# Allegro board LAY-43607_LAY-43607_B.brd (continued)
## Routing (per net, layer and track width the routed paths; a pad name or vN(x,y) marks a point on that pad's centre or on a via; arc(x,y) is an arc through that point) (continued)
D1_MBG0: length 138.4
  TOP w0.137: v2(78.17,33.32) 77.74,33.32 77.49,33.07 76.53,33.07 76.37,33.23 76.37,33.37 76.21,33.54 75.98,33.54 75.82,33.37 75.82,33.23 75.66,33.07 74.4,33.07 73.23,34.23 72.87,34.23 72.66,34.45 72.66,34.96 U14.E27 ; R130.1 40.67,14.18 40.91,13.94 40.91,13.74 40.77,13.6 40.51,13.6 40.37,13.47 40.37,13.27 40.51,13.14 40.95,13.14 41.09,13 41.09,12.77 41.09,12.77 41.09,12.41 41.09,12.41 41.09,12.07 42.68,10.48 42.68,10.47 43.44,9.71 44.45,9.71 44.59,9.57 44.59,9.38 v1(44.52,9.31)
  L3_INT_1 w0.107: v1(90.44,9.31) 90.06,8.92 89.48,8.92 88.26,10.15 88.08,10.15 87.84,10.39 87.84,11.18 86.34,12.69 86.34,14.4 85.9,14.83 85.9,15.51 86.1,15.7 86.1,19.42 82.41,23.1 81.55,23.1 81.28,23.36 81.28,24.23 79.54,25.97 79.54,26.96 79.04,27.47 76.92,27.47 76.83,27.56 76.83,28.7 76.98,28.85 77.57,28.85 77.72,29.01 77.72,29.23 77.57,29.39 76.98,29.39 76.83,29.54 76.83,29.76 76.98,29.92 77.57,29.92 77.72,30.08 77.72,30.3 77.57,30.45 76.98,30.45 76.83,30.61 76.83,30.83 76.98,30.99 77.57,30.99 77.72,31.14 77.72,31.36 77.57,31.52 76.98,31.52 76.83,31.68 76.83,32.36 75.91,33.27 75.9,33.27 75.03,34.15 73.28,34.15 73.04,34.39 73.04,36.71 73.34,37.01 76.08,37.01 76.58,36.51 76.58,36.28 76.43,36.12 75.63,36.12 75.47,35.97 75.47,35.74 75.63,35.59 76.43,35.59 76.58,35.43 76.58,35.21 76.43,35.05 75.63,35.05 75.47,34.9 75.47,34.68 75.63,34.52 76.43,34.52 76.58,34.36 76.58,34.27 77.06,33.79 77.69,33.79 v2(78.17,33.32) ; v1(78.96,9.31) 78.96,9.57 78.58,9.95 78.58,10.37 78.45,10.51 77.7,10.51 77.59,10.61 77.59,10.99 77.78,11.17 77.78,11.18 78.17,11.57 78.17,11.9 77.96,12.11 77.16,12.11 76.97,12.29 76.73,12.29 76.55,12.11 76.3,12.11 76.12,12.29 75.88,12.29 75.69,12.11 75.45,12.11 75.27,12.29 75.02,12.29 74.84,12.11 74.6,12.11 74.41,12.29 74.17,12.29 73.99,12.11 71.67,12.11 71.58,12.2 70.93,12.2 70.83,12.11 70.15,12.11 69.86,11.82 69.86,10.34 68.41,8.89 68.11,8.89 67.69,9.31 v1(67.48,9.31) 67.48,9.58 67.3,9.77 67.12,9.77 67.06,9.82 67.06,10.31 66.85,10.52 66.52,10.52 66.51,10.53 65.35,10.53 63.3,8.49 63.3,7.2 63.11,7.01 62.1,7.01 61.79,7.31 61,7.31 60.89,7.42 60.89,7.58 60.78,7.68 60.57,7.68 60.46,7.58 60.46,7.42 60.36,7.31 59.85,7.31 59.68,7.48 59.68,7.88 59.27,8.29 59.27,8.44 59.66,8.83 59.66,8.98 59.51,9.13 59.36,9.13 58.97,8.74 58.82,8.74 58.65,8.91 56.65,8.91 56.25,9.31 v1(56,9.31)
  L4_INT_2 w0.107: v1(56,9.31) 55.77,9.31 55.37,8.9 55,8.9 54.57,9.34 53.04,9.34 52.71,9.02 52.71,7.22 52.61,7.11 52.21,7.11 51.61,7.72 49.85,7.72 49.48,8.09 48.36,8.09 47.84,7.57 47.16,7.57 46.48,8.26 46.48,8.75 46.3,8.92 44.52,8.92 44.41,9.04 44.41,9.19 v1(44.52,9.31)
  BOTTOM w0.137: v1(78.96,9.31) 79.2,9.31 79.6,8.91 79.61,8.91 79.61,8.91 79.93,8.91 80.19,8.65 80.85,8.65 81.88,7.62 82.47,7.62 82.77,7.31 83.13,7.31 83.51,7.69 88.14,7.69 88.21,7.75 88.22,7.75 88.23,7.76 88.35,7.76 88.96,8.37 88.96,8.48 89.39,8.91 89.81,8.91 90.04,8.67 90.04,8.34 90.28,8.11 90.61,8.11 90.84,8.34 90.84,8.91 v1(90.44,9.31)
D1_MBG1: length 99.9
  TOP w0.137: U14.E28 72.22,34.22 73.12,33.33 73.33,33.33 74.11,32.55 v2(82.18,32.55) ; R132.1 53.43,3.62 v2(56.32,3.62)
  L3_INT_1 w0.107: v2(82.18,32.55) 87.44,32.55 90.25,29.74 93.3,29.74 102.37,20.67 102.37,8.6 v2(98.89,5.12)
  L4_INT_2 w0.107: v2(98.89,5.12) 97.39,3.62 v2(56.32,3.62)
D1_MCAS_B: length 134.6
  TOP w0.137: v2(82.19,8.92) 82.3,8.92 82.32,8.91 83.36,8.91 U16.M8 83.91,9.31 84.31,9.71 85.01,9.71 85.3,10 86.84,10 86.97,10.14 86.97,10.7 87.11,10.83 87.38,10.83 87.52,10.7 87.52,10.14 87.66,10 88.21,10 88.5,9.71 91.99,9.71 92.18,9.9 92.38,9.9 93.46,8.82 93.65,8.82 93.84,9.01 93.84,9.2 92.76,10.28 92.76,10.48 93.21,10.92 93.86,10.92 94.28,10.51 94.6,10.51 94.84,10.27 94.84,9.79 94.93,9.7 95.1,9.7 95.24,9.56 v1(95.24,9.31) ; v2(95.51,21.77) 65.19,21.77 56.96,30 56.96,33.74 U14.AC28
  L3_INT_1 w0.107: v2(95.51,21.77) 96.58,21.77 98.36,19.99 98.36,11.84 96.25,9.72 95.66,9.72 v1(95.24,9.31)
  L4_INT_2 w0.107: v2(82.19,8.92) 79.59,8.92 79.35,9.16 79.35,9.49 79.12,9.72 78.03,9.72 77.78,9.47 77.78,9.3 77.38,8.89 77.14,8.89 77.04,9 77.04,9.26 76.93,9.36 76.72,9.36 76.61,9.26 76.61,9 76.5,8.89 76.29,8.89 76.18,9 76.18,9.26 76.04,9.39 75.89,9.39 75.75,9.26 75.75,9 75.65,8.89 75.43,8.89 75.33,9 75.33,9.26 75.19,9.39 75.04,9.39 74.9,9.26 74.9,9 74.79,8.89 74.58,8.89 74.47,9 74.47,9.26 74.34,9.39 74.19,9.39 74.05,9.26 74.05,9.03 73.94,8.92 72.75,8.92 72.36,9.31 v1(72.28,9.31) 71.87,9.72 64.52,9.72 64.18,9.38 64.18,7.57 64.07,7.46 63.59,7.46 63.46,7.59 63.46,7.92 63.05,8.33 63.05,9.36 62.69,9.72 61.21,9.72 v1(60.8,9.31)
  BOTTOM w0.137: v1(60.8,9.31) 60.37,8.88 57.71,8.88 57.68,8.91 56.64,8.91 56.4,8.66 56.4,8.34 56.17,8.11 55.85,8.11 55.84,8.11 55.84,8.11 55.6,7.87 55.6,7.87 55.6,7.86 55.6,7.54 55.37,7.31 55.04,7.31 54.81,7.54 54.31,7.54 53.99,7.22 53.99,6.51 53.84,6.36 53.47,6.36 53.33,6.5 53.33,6.84 51.98,8.19 50.67,8.19 50.52,8.34 50.52,8.67 50.29,8.91 49.72,8.91 v1(49.32,9.31) 48.92,8.91 47.81,8.91 46.78,7.88 46.78,4.79 R125.1
D1_MCKE0: length 136.9
  TOP w0.137: v2(79.56,34.59) 75.21,34.59 74.85,34.23 74.18,34.23 U14.C28 ; v1(44.52,10.91) 44.52,11.12 44.12,11.52 44.12,11.92 43.93,12.11 43.55,12.11 42.89,12.77 42.89,14.75 42.39,15.24 42.28,15.24 41.77,15.75 41.77,16.13 41.15,16.76 R131.1
  L3_INT_1 w0.107: v2(79.56,34.59) 80.64,34.59 80.81,34.76 80.81,36.22 80.62,36.41 79.17,36.41 79.02,36.25 79.02,36.01 78.86,35.85 78.64,35.85 78.48,36.01 78.48,36.25 78.33,36.41 77.98,36.41 77.88,36.3 77.88,35.09 79.84,33.13 79.84,32.14 80,31.98 82.18,31.98 82.31,31.85 82.31,31.58 82.18,31.45 80,31.45 79.84,31.29 79.84,31.07 80,30.92 82.18,30.92 82.33,30.76 82.33,30.54 82.18,30.38 80,30.38 79.84,30.23 79.84,29.61 80.69,28.76 80.91,28.76 81.89,29.75 82.11,29.75 82.27,29.59 82.27,29.37 81.28,28.39 81.28,28.17 81.44,28.01 81.66,28.01 82.65,29 82.87,29 83.02,28.84 83.02,28.62 82.04,27.63 82.04,27.41 82.19,27.26 82.42,27.26 83.4,28.24 83.62,28.24 83.78,28.09 83.78,27.86 82.8,26.89 82.8,26.74 88.68,20.85 88.68,20.49 88.56,20.37 88.17,20.37 88.04,20.24 88.04,20.06 88.17,19.94 88.56,19.94 88.68,19.81 88.68,14.42 88.99,14.11 89.38,14.11 89.62,13.87 89.62,12.71 90.04,12.29 90.04,11.66 90.44,11.26 v1(90.44,10.91) ; v1(44.52,10.91) 44.9,10.52 45.58,10.52 45.78,10.33 45.78,9.69 46.02,9.45 47.65,9.45 47.98,9.77 47.98,11.17 48.51,11.7 48.51,13.07 48.46,13.11 48.46,13.79 48.76,14.09 51.59,14.09 54.36,11.32 54.38,11.32 54.39,11.32 55.59,11.32 v1(56,10.91)
  L4_INT_2 w0.107: v1(56,10.91) 56.07,10.91 56.48,10.49 57.52,10.49 57.73,10.29 57.73,9.82 57.89,9.66 58.54,9.66 58.87,9.99 58.87,10.82 58.98,10.93 59.45,10.93 59.82,11.29 62.47,11.29 63.05,10.72 63.73,10.72 63.84,10.82 63.84,11.47 63.95,11.58 64.16,11.58 64.27,11.47 64.27,10.82 64.37,10.72 65.95,10.72 66.53,11.29 67.09,11.29 v1(67.48,10.91) 67.87,11.29 71.91,11.29 72.01,11.4 72.01,11.67 72.12,11.77 72.33,11.77 72.44,11.67 72.44,11.4 72.55,11.29 73.68,11.29 73.79,11.4 73.79,11.84 73.9,11.94 74.13,11.94 74.32,11.75 74.32,11.4 74.43,11.29 74.72,11.29 74.83,11.4 74.83,12.14 74.93,12.24 75.36,12.24 75.47,12.14 75.47,11.4 75.57,11.29 76.02,11.29 76.54,10.77 77.46,10.77 77.99,11.29 78.58,11.29 v1(78.96,10.91) 79.35,10.52 82.05,10.52 82.58,11.05 82.58,11.07 82.84,11.32 84.97,11.32 85.34,11.7 85.57,11.7 85.68,11.59 85.68,11.13 85.78,11.02 86,11.02 86.1,11.13 86.1,11.59 86.21,11.7 86.43,11.7 86.53,11.59 86.53,11.13 86.64,11.02 86.85,11.02 86.96,11.13 86.96,11.59 87.07,11.7 87.58,11.7 87.98,11.29 88.32,11.29 88.72,11.7 89.11,11.7 89.48,11.32 89.8,11.32 90.13,11.65 90.28,11.65 90.44,11.49 v1(90.44,10.91)
D1_MCLK0_N: length 131.7
  TOP w0.124: v2(89.32,25.92) 89.01,25.62 87.87,25.62 87.68,25.81 87.68,26.81 87.32,27.17 86.8,27.17 86.44,26.81 86.44,25.81 86.25,25.62 83.03,25.62 82.54,26.11 78.64,26.11 77.85,26.9 74.45,26.9 73.93,26.38 70.24,26.38 68.77,27.86 68.29,27.86 67.51,27.08 67.25,27.08 67.06,27.27 67.06,27.54 67.83,28.31 67.83,28.81 67.18,29.47 64.81,29.47 64.04,30.23 64.04,33.91 64.58,34.45 64.58,35.04 U14.R27
  L3_INT_1 w0.094: v1(95.24,10.91) 95.24,11.17 94.86,11.55 94.86,14.65 95.18,14.96 95.55,14.96 95.99,15.4 95.99,17.63 95.26,18.35 95.26,20.6 93.85,22.02 93.85,22.25 94.64,23.04 94.64,23.58 94.25,23.96 93.71,23.96 92.93,23.17 92.69,23.17 92.53,23.34 92.53,23.57 93.31,24.36 93.31,24.9 92.93,25.28 92.39,25.28 91.6,24.5 91.37,24.5 90.26,25.61 89.63,25.61 v2(89.32,25.92)
  BOTTOM w0.124: R137.1 45.97,5.01 45.97,5.75 46.41,6.19 46.41,8.14 47.64,9.37 47.64,9.87 48.27,10.51 48.92,10.51 v1(49.32,10.91) 49.57,10.91 49.96,10.52 50.46,10.52 50.69,10.75 51.01,10.75 51.64,11.38 53.26,11.38 53.52,11.64 53.52,12.16 53.9,12.54 54.15,12.54 54.6,12.1 56.74,12.1 57.19,11.65 57.19,10.23 57.76,9.67 59,9.67 59.84,10.5 60.44,10.5 60.8,10.86 v1(60.8,10.91) 61.19,10.52 61.76,10.52 62.23,10.98 64.04,10.98 64.83,11.78 66.72,11.78 68.53,13.58 69.64,13.58 69.89,13.34 69.89,12.05 71.09,10.85 71.09,10.75 71.32,10.52 71.89,10.52 v1(72.28,10.91) 72.03,11.15 72.03,11.97 72.16,12.09 72.79,12.09 72.82,12.12 74.52,12.12 74.65,11.99 74.65,11.58 74.92,11.31 75.48,11.31 75.79,11.62 75.79,11.99 75.91,12.12 79.14,12.12 79.5,12.47 80.61,12.47 82.57,10.52 83.26,10.52 83.5,10.75 83.61,10.75 v1(83.76,10.91) 83.76,11.09 83.48,11.37 83.48,11.81 83.84,12.17 85.74,12.17 85.86,12.04 85.86,11.5 86.17,11.19 86.81,11.19 87.13,11.5 87.13,12.04 87.25,12.17 89.77,12.17 90.64,11.3 91.4,11.3 91.42,11.28 91.92,11.28 92.69,10.51 94.49,10.51 94.5,10.52 94.6,10.52 94.61,10.52 94.86,10.52 v1(95.24,10.91)
D1_MCLK0_P: length 131.8
  TOP w0.124: U14.R28 63.74,34.11 63.74,34.08 63.72,34.06 63.72,30.1 64.68,29.15 67.05,29.15 67.51,28.68 67.51,28.44 66.74,27.67 66.74,27.14 67.12,26.76 67.65,26.76 68.42,27.54 68.63,27.54 70.11,26.06 74.06,26.06 74.58,26.58 77.71,26.58 78.51,25.79 82.41,25.79 82.9,25.3 86.38,25.3 86.76,25.67 86.76,26.68 86.93,26.85 87.18,26.85 87.36,26.68 87.36,25.67 87.74,25.3 89.03,25.3 v2(89.32,25.01)
  L3_INT_1 w0.094: v2(89.32,25.01) 89.54,25.24 90.1,25.24 91.22,24.13 91.76,24.13 92.54,24.91 92.78,24.91 92.94,24.75 92.94,24.52 92.16,23.73 92.16,23.19 92.54,22.8 93.08,22.8 93.87,23.59 94.1,23.59 94.26,23.43 94.26,23.19 93.48,22.4 93.48,21.86 94.89,20.45 94.89,18.2 95.62,17.47 95.62,15.55 95.4,15.33 95.02,15.33 94.49,14.8 94.49,11.89 94.49,11.4 94.86,11.03 94.86,10.58 94.76,10.48 94.52,10.48 94.44,10.56 v1(94.44,10.91)
  BOTTOM w0.124: R138.1 45.4,4.74 45.65,4.99 45.65,5.88 46.09,6.32 46.09,8.27 47.32,9.51 47.32,10.01 47.5,10.19 47.5,10.36 47.43,10.43 47.43,10.64 47.56,10.76 47.8,10.76 47.85,10.71 48.03,10.71 48.22,10.91 v1(48.52,10.91) 48.91,11.3 50.46,11.3 50.69,11.07 50.88,11.07 51.51,11.7 53.08,11.7 53.2,11.82 53.2,12.3 53.78,12.87 54.28,12.87 54.73,12.42 56.87,12.42 57.51,11.78 57.51,10.37 57.89,9.99 58.87,9.99 59.05,10.17 59.05,10.47 59.16,10.58 59.47,10.58 59.71,10.82 59.72,10.82 59.81,10.91 v1(60,10.91) 60.39,11.29 60.63,11.29 60.64,11.3 63.9,11.3 64.7,12.1 66.59,12.1 68.4,13.9 69.78,13.9 70.21,13.47 70.21,12.18 70.48,11.91 70.66,11.91 70.73,11.98 71.01,11.98 71.2,11.79 71.2,11.55 71.11,11.46 71.11,11.28 v1(71.48,10.91) 71.71,11.14 71.71,12.1 72.03,12.41 72.66,12.41 72.68,12.44 74.66,12.44 74.97,12.13 74.97,11.75 75.09,11.63 75.34,11.63 75.47,11.75 75.47,12.13 75.78,12.44 79.01,12.44 79.36,12.79 80.75,12.79 81.68,11.86 81.85,11.86 81.93,11.94 82.16,11.94 82.31,11.79 82.31,11.61 82.2,11.51 82.2,11.34 82.63,10.91 v1(82.96,10.91) 82.96,11.02 83.15,11.2 83.15,12.01 83.62,12.49 85.87,12.49 86.18,12.18 86.18,11.63 86.31,11.51 86.68,11.51 86.81,11.63 86.81,12.18 87.12,12.49 89.9,12.49 90.77,11.62 91.54,11.62 91.56,11.6 92.05,11.6 92.82,10.83 93.07,10.83 93.2,10.95 93.2,11.03 93.32,11.16 93.7,11.16 93.82,11.03 93.82,10.95 93.94,10.83 94.36,10.83 v1(94.44,10.91)
D1_MCS_B0: length 138.1
  TOP w0.137: U14.AB27 58.26,35.03 58.26,34.51 57.97,34.22 57.97,29.62 65.37,22.21 93.62,22.21 93.76,22.35 93.76,22.89 93.62,23.03 v2(91.35,23.03) ; v1(48.52,10.11) 48.4,10.11 48.12,10.39 47.29,10.39 46.26,9.36 46.26,5.17 45.62,4.54 45.62,4.34 45.88,4.08 R136.1 ; U16.L7 82.33,10.11 v2(82.33,10.1) 82.33,11.78 81.86,12.25 81.59,12.25 81.45,12.11 81.45,11.87 81.7,11.62 81.7,11.45 81.58,11.33 81.41,11.33 81.21,11.53 81.04,11.53 80.92,11.41 80.92,11.24 81.12,11.03 81.12,10.86 81,10.74 80.83,10.74 80.58,10.99 80.41,10.99 79.93,10.51 77.8,10.51 77.54,10.25 76.74,10.25 76.59,10.4 76.26,10.4 75.93,10.74 75.22,10.74 75.1,10.62 75.1,10.27 74.98,10.15 74.81,10.15 74.69,10.27 74.69,10.62 74.57,10.74 74.4,10.74 74.28,10.62 74.28,10.27 74.16,10.15 73.99,10.15 73.87,10.27 73.87,10.62 73.75,10.74 73.47,10.74 73.25,10.51 71.88,10.51 U565.L7 70.85,10.11 70.85,10.1 70.44,10.51 65.06,10.51 64.51,11.06 64.51,11.35 63.23,12.62 62.43,12.62 61.91,12.11 60.64,12.11 60.4,11.87 60.4,11.48 60.39,11.48 60.22,11.31 59.84,11.31 59.56,11.03 58.29,11.03 58.14,10.88 58.14,10.25 58.28,10.11 v1(60,10.11)
  L3_INT_1 w0.107: v2(91.35,23.03) 94.04,20.34 94.04,20.07 94.22,19.88 94.22,16.65 93.44,15.87 93.44,13.16 93.43,13.16 arc(93.44,13.11) 93.47,13.06 94.04,12.5 94.04,10.51 v1(94.44,10.11)
  BOTTOM w0.137: v1(48.52,10.11) 48.92,9.71 50.29,9.71 51.36,8.64 52.16,8.64 52.74,8.06 54.9,8.06 55.6,8.76 55.6,10.28 55.84,10.51 56.16,10.51 56.4,10.27 56.4,9.85 56.54,9.71 56.96,9.71 57.38,9.29 59.18,9.29 v1(60,10.11) ; v2(82.33,10.1) 83.19,10.1 83.6,10.51 85.86,10.51 85.87,10.52 86.84,10.52 86.87,10.55 87.39,10.55 88.02,11.18 88.87,11.18 89,11.31 89.9,11.31 90.04,11.17 90.04,10.75 90.28,10.51 91.36,10.51 91.37,10.51 91.41,10.51 91.8,10.11 92.17,10.11 92.31,9.96 92.31,9.48 92.45,9.34 92.71,9.34 92.85,9.48 92.85,9.97 92.99,10.11 v1(94.44,10.11)
D1_MDIC_0: length 2.9
  TOP w0.137: U14.P28 65.02,34.22 64.67,33.87 64.67,32.69 64.93,32.43 R141.2
D1_MDIC_1: length 2.9
  TOP w0.137: U14.U28 63.11,34.11 63.11,33.22 62.82,32.93 R140.2
D1_MDM0: length 45.7
  TOP w0.137: v2(84.42,33.76) 84.42,34.2 80.59,38.02 76.3,38.02 76.09,38.23 74.98,38.23 U14.B23 ; v2(93.88,14.89) 93.89,14.91 U15.E7
  L4_INT_2 w0.107: v2(84.42,33.76) 85.3,32.88 85.5,32.88 85.9,33.28 85.98,33.28 86.23,33.03 86.23,32.9 85.73,32.4 85.73,32.27 85.91,32.1 86.04,32.1 86.46,32.52 86.61,32.52 88.65,30.47 88.65,30.18 88.89,29.94 89.19,29.94 89.37,29.76 89.37,29.05 89.5,28.92 89.65,28.92 89.91,29.17 90.09,29.17 90.21,29.05 90.21,28.87 89.91,28.58 89.91,28.4 90.04,28.27 90.22,28.27 90.54,28.6 90.67,28.6 90.81,28.45 90.81,28.27 90.64,28.1 90.64,27.59 93.26,24.98 93.26,24.69 93.38,24.56 93.66,24.56 93.72,24.51 93.72,24.19 93.67,24.14 93.38,24.14 93.26,24.01 93.26,23.83 93.38,23.71 93.65,23.71 93.78,23.58 93.78,23.41 93.65,23.28 93.38,23.28 93.26,23.16 93.26,22.98 93.38,22.86 93.65,22.86 93.78,22.73 93.78,22.55 93.65,22.43 93.38,22.43 93.26,22.3 93.26,22.13 93.38,22 93.65,22 93.78,21.88 93.78,21.7 93.65,21.58 93.38,21.58 93.26,21.45 93.26,21.27 93.38,21.15 93.65,21.15 93.78,21.02 93.78,20.85 93.65,20.72 93.38,20.72 93.26,20.6 93.26,20.42 93.63,20.05 93.63,19.67 93.26,19.3 93.26,17.31 94.23,16.33 94.23,15.27 94.72,14.79 94.72,14.53 94.56,14.37 94.4,14.37 v2(93.88,14.89)
D1_MDM1: length 48.6
  TOP w0.137: U15.E2 90.84,14.51 91.55,14.51 92.02,14.98 92.57,14.98 92.61,15.01 v2(93,15.01) ; v3(69.42,39) U14.H22
  BOTTOM w0.137: v3(69.42,39) 69.7,39 70.07,38.62 70.35,38.62 70.6,38.37 70.6,38.05 70.86,37.79 71.27,37.79 71.41,37.66 71.41,37.22 71.63,37 71.99,37 72.22,36.76 72.22,36.49 72.25,36.46 72.25,36.44 72.47,36.22 72.79,36.22 73.02,35.99 73.02,35.63 72.63,35.24 72.63,33.32 78.9,27.05 78.9,27.03 81.35,24.57 84.22,24.57 87.62,21.18 87.62,14.84 87.99,14.46 88.44,14.46 88.8,14.11 89.5,14.11 89.64,13.97 89.64,13.44 89.78,13.31 90.28,13.31 90.44,13.14 90.44,12.64 90.58,12.51 91.18,12.51 91.82,11.86 92.56,11.86 93.19,12.5 93.22,12.5 93.44,12.72 93.44,12.91 93.33,13.03 93.33,13.81 93,14.14 v2(93,15.01)
D1_MDM2: length 49.1
  TOP w0.137: v3(72.63,36.59) U14.E25 ; U16.E7 v2(83.36,15.31)
  L4_INT_2 w0.107: v3(72.63,36.59) 73.01,36.21 73.01,35.7 73.28,35.44 74.11,35.44 74.83,36.15 76.74,36.15 76.87,36.03 76.87,30.22 82.02,25.07 82.02,23.98 82.46,23.54 82.61,23.54 83,23.94 83.15,23.94 83.3,23.79 83.3,23.63 82.91,23.24 82.91,23.09 83.06,22.94 83.21,22.94 83.61,23.33 83.76,23.33 83.91,23.18 83.91,23.03 83.52,22.64 83.52,22.49 86.25,19.75 86.69,19.75 86.84,19.6 86.84,19.31 86.74,19.2 85.96,19.2 85.86,19.09 85.86,18.88 85.96,18.77 86.74,18.77 86.84,18.66 86.84,18.45 86.74,18.34 85.96,18.34 85.86,18.24 85.86,18.02 85.96,17.92 86.74,17.92 86.84,17.81 86.84,17.6 86.74,17.49 85.96,17.49 85.86,17.38 85.86,17.17 85.96,17.06 86.74,17.06 86.84,16.96 86.84,15.71 86.71,15.58 86.03,15.58 85.87,15.42 85.87,14.91 86.03,14.75 86.69,14.75 86.75,14.69 86.75,13.63 86.47,13.35 85.63,13.35 85.41,13.58 85.41,14.82 85.3,14.92 84.68,14.92 84.57,14.82 84.57,14.2 84.46,14.09 83.89,14.09 83.74,14.23 83.74,14.67 83.74,14.67 83.74,14.92 v2(83.36,15.31)
D1_MDM3: length 46.5
  TOP w0.137: U14.J25 69.02,36.99 v3(69.43,36.59) ; v2(81.66,16.37) 82.56,15.47 82.56,13.94 82.39,13.77 82.13,13.77 81.96,13.94 81.96,15.12 81.78,15.31 79.36,15.31 U16.E2
  BOTTOM w0.137: v3(69.43,36.59) 69.43,36.49 69.84,36.09 69.84,35.45 69.71,35.32 69.71,33.37 70.19,32.89 70.19,31.8 70.41,31.58 70.61,31.58 70.92,31.9 71.14,31.9 71.34,31.7 71.34,31.44 71.04,31.14 71.04,30.95 73.47,28.53 73.47,28.25 73.26,28.05 73.26,26.73 73.6,26.39 74.19,26.39 74.38,26.58 74.38,27.76 74.52,27.9 74.79,27.9 74.93,27.76 74.93,26.53 75.06,26.39 75.4,26.39 75.54,26.53 75.54,26.87 75.67,27 75.95,27 76.08,26.87 76.08,26.53 76.22,26.39 76.56,26.39 76.7,26.26 76.7,24.78 77.04,24.45 77.83,24.45 80.39,21.88 82.49,21.88 83.4,20.97 83.4,20.68 83.6,20.49 83.78,20.49 83.91,20.35 83.91,20.08 83.78,19.94 83.54,19.94 83.4,19.8 83.4,17.63 82.31,16.53 82.31,16.24 81.67,15.6 81.4,15.6 81.26,15.74 81.26,16.24 81.4,16.38 81.66,16.38 v2(81.66,16.37)
D1_MDM4: length 47
  TOP w0.137: U14.V25 61.42,36.6 v3(61.42,36.59) ; U17.E7 v2(60.4,15.31)
  BOTTOM w0.137: v2(60.4,15.31) 60,15.31 59.83,15.48 59.83,17.01 60.13,17.31 60.83,17.31 60.92,17.22 60.92,16.9 61,16.82 61.39,16.82 61.53,16.96 61.53,17.75 61.45,17.82 60.95,17.82 60.8,17.98 60.8,18.79 61,18.99 62.3,18.99 62.98,19.68 62.98,20.38 63.47,20.87 64.06,20.87 64.3,20.64 64.75,20.64 65.04,20.93 65.04,21.58 64.86,21.76 63.85,21.76 63.53,22.09 63.53,22.6 63.38,22.75 62.76,22.75 62.6,22.59 62.6,20.37 62.46,20.24 62.23,20.24 62.05,20.42 62.05,22.59 61.89,22.75 61.51,22.75 61.3,22.96 61.3,23.62 61.43,23.75 62.79,23.75 62.93,23.89 62.93,24.13 62.76,24.3 61.43,24.3 61.3,24.44 61.3,24.71 61.43,24.85 62.76,24.85 62.9,24.99 62.9,25.21 62.71,25.4 61.43,25.4 61.3,25.54 61.3,25.81 61.43,25.95 62.36,25.95 62.52,26.1 62.52,26.63 62.33,26.81 61.78,26.81 61.66,26.94 61.66,27.36 61.52,27.5 61.32,27.5 61.19,27.64 61.19,27.91 61.32,28.05 61.52,28.05 61.66,28.19 61.66,29.37 61.52,29.51 61.52,30.75 61.3,30.97 61.3,31.3 61.55,31.56 61.55,31.81 61.3,32.07 61.3,32.39 61.55,32.65 61.55,32.84 61.16,33.24 61.16,33.62 61.43,33.9 61.43,34.07 61.31,34.19 61.22,34.19 61.1,34.31 61.1,34.48 61.22,34.6 61.31,34.6 61.43,34.72 61.43,34.99 61.03,35.39 61.03,36.46 61.16,36.59 v3(61.42,36.59)
D1_MDM5: length 46.8
  TOP w0.137: v3(57.42,38.19) 57.42,38.19 U14.AD24 ; U17.E2 v2(55.6,15.31)
  L4_INT_2 w0.107: v3(57.42,38.19) 57.07,37.84 55.68,37.84 55.65,37.86 51.09,37.86 50.71,37.48 50.71,34.09 50.3,33.68 50.3,33.25 50.62,32.93 52,32.93 52.29,33.22 52.95,33.22 53.69,32.48 53.69,25.63 52.44,24.38 52.44,17.22 51.83,16.61 51.83,12.75 51.46,12.39 51.46,11.23 51.6,11.09 52.05,11.09 52.18,11.23 52.18,12.26 52.46,12.54 53.31,12.54 54.09,13.32 54.09,15.46 54.32,15.69 55.22,15.69 v2(55.6,15.31)
D1_MDM6: length 47.6
  TOP w0.137: U18.E7 48.22,15.2 48.22,15.43 47.99,15.66 47.46,15.66 47.23,15.9 47.23,16.43 47.03,16.63 45.96,16.63 45.76,16.43 45.76,15.38 46.01,15.13 v2(47.63,15.13) ; U14.AC23 v3(57.42,38.99)
  BOTTOM w0.137: v3(57.42,38.99) 57.42,38.72 57.05,38.35 57.05,38.09 56.78,37.82 56.48,37.82 56.22,37.56 56.22,37.27 55.98,37.02 54.51,37.02 53.88,36.38 53.68,36.38 53.46,36.61 53.26,36.61 53.07,36.41 53.07,36.22 53.29,35.99 53.29,35.8 52.89,35.4 52.89,35.24 52.73,35.08 52.61,35.08 52.45,34.92 52.45,34.69 52.61,34.53 52.73,34.53 52.89,34.37 52.89,34.14 52.73,33.98 52.61,33.98 52.45,33.82 52.45,33.59 52.61,33.43 52.73,33.43 52.89,33.27 52.89,31.91 52.76,31.77 52.62,31.77 52.48,31.64 52.48,31.36 52.62,31.22 52.78,31.22 52.92,31.09 52.92,30.72 52.78,30.58 52.31,30.58 52.17,30.45 52.17,30.17 52.31,30.03 52.76,30.03 52.89,29.9 52.89,29.62 52.76,29.49 52.31,29.49 52.17,29.35 52.17,29.07 52.31,28.94 52.76,28.94 52.89,28.8 52.89,28.53 52.76,28.39 52.63,28.39 52.49,28.25 52.49,26.89 50.04,24.44 49.81,24.44 49.35,24.9 49.12,24.9 48.96,24.74 48.96,24.51 49.42,24.05 49.42,23.82 49.26,23.66 49.03,23.66 48.56,24.14 48.36,24.14 48.17,23.95 48.17,23.75 48.65,23.27 48.65,23.05 48.37,22.77 48.37,21.57 48.21,21.41 48,21.41 47.83,21.25 47.83,21.02 48,20.86 48.21,20.86 48.37,20.7 48.37,20.47 48.21,20.31 48,20.31 47.83,20.15 47.83,19.92 48,19.76 48.21,19.76 48.37,19.6 48.37,19.37 48.21,19.21 48,19.21 47.83,19.05 47.83,18.83 48,18.67 48.21,18.67 48.37,18.5 48.37,17.82 48.13,17.58 47.79,17.58 47.56,17.35 47.56,17.02 47.79,16.78 48.14,16.78 48.37,16.56 48.37,15.86 v2(47.63,15.13)
D1_MDM7: length 48.2
  TOP w0.137: U18.E2 v2(44.12,15.31) ; U14.AH24 53.42,37.39 52.58,37.39 50.02,34.84 v2(50.02,32.53)
  L4_INT_2 w0.107: v2(50.02,32.53) 50.02,31.39 50.84,30.57 50.84,30.14 50.99,29.99 51.21,29.99 51.37,29.83 51.37,29.61 51.21,29.45 50.99,29.45 50.84,29.3 50.84,29.08 50.99,28.92 51.24,28.92 51.39,28.76 51.39,28.54 51.24,28.39 50.99,28.39 50.84,28.23 50.84,27.04 49.5,25.71 49.5,25.28 49.65,25.13 50.1,25.13 50.25,24.97 50.25,24.75 50.1,24.59 49.65,24.59 49.5,24.44 49.5,24.22 49.65,24.06 50.1,24.06 50.25,23.9 50.25,23.68 50.1,23.53 49.65,23.53 49.5,23.37 49.5,23.15 49.65,22.99 50.1,22.99 50.25,22.84 50.25,22.62 50.1,22.46 49.65,22.46 49.5,22.3 49.5,22.08 49.65,21.93 50.1,21.93 50.25,21.77 50.25,21.55 50.1,21.39 49.65,21.39 49.5,21.24 49.5,21.02 49.65,20.86 50.1,20.86 50.25,20.7 50.25,20.48 50.1,20.33 49.65,20.33 49.5,20.17 49.5,19.18 49.06,18.74 49.06,16 48.56,15.51 45.83,15.51 44.92,14.6 44.92,13.8 44.81,13.69 43.54,13.69 43.3,13.45 43.3,12.13 43.1,11.94 42.13,11.94 41.92,12.15 41.92,14.87 42.75,15.7 43.73,15.7 v2(44.12,15.31)
D1_MDM8: length 49
  TOP w0.137: U565.E7 v2(71.88,15.31) ; U14.P24 65.42,37.4 v3(65.43,37.4)
  L4_INT_2 w0.107: v3(65.43,37.4) 65.43,37.12 65.84,36.7 65.84,34.59 65.73,34.48 65.35,34.48 65.24,34.38 65.24,34.18 65.36,34.06 65.73,34.06 65.84,33.95 65.84,33.12 65.59,32.87 65.59,32.69 65.77,32.51 65.77,32.3 66.32,31.76 66.32,31.59 65.93,31.2 65.93,31.05 66.07,30.91 66.22,30.91 66.62,31.3 66.77,31.3 66.88,31.2 66.88,31.05 66.57,30.74 66.57,30.41 66.67,30.3 67.02,30.3 67.32,30.6 67.47,30.6 67.77,30.3 68.63,29.44 68.63,29.44 68.79,29.28 68.79,27.9 68.69,27.79 68.06,27.79 67.95,27.68 67.95,27.47 68.06,27.36 68.69,27.36 68.84,27.2 68.84,26.32 69.09,26.08 69.09,23.68 69.27,23.5 70.21,23.5 70.37,23.34 70.37,23.14 70.26,23.03 69.84,23.03 69.73,22.92 69.73,22.71 69.84,22.6 70.26,22.6 70.37,22.5 70.37,22.28 70.26,22.18 69.84,22.18 69.73,22.07 69.73,21.86 69.84,21.75 70.26,21.75 70.37,21.64 70.37,21.43 70.26,21.32 69.84,21.32 69.73,21.22 69.73,21 69.84,20.9 70.26,20.9 70.37,20.79 70.37,20.58 70.26,20.47 69.84,20.47 69.73,20.36 69.73,19.88 69.92,19.69 71.21,19.69 71.32,19.58 71.32,19.37 71.21,19.26 69.84,19.26 69.73,19.16 69.73,18.99 69.93,18.79 71.11,18.79 71.31,18.58 71.31,17.06 71,16.75 70,16.75 69.7,16.45 68.94,16.45 68.84,16.35 68.84,16.02 68.97,15.89 70.01,15.89 70.12,15.78 70.12,15.57 70.01,15.46 69.38,15.46 69.27,15.35 69.27,14.96 69.48,14.75 70.2,14.75 70.46,15.01 70.46,16.11 70.79,16.44 71.04,16.44 71.25,16.22 71.25,14.74 71.36,14.63 71.46,14.63 71.88,15.05 v2(71.88,15.31)
D1_MDQ0: length 45.7
  TOP w0.137: v2(83.86,36.01) 83.86,36.06 80.96,38.95 76.26,38.95 76.23,38.98 74.24,38.98 U14.C22 ; U15.G2 v2(90.04,12.91)
  L4_INT_2 w0.107: v2(90.04,12.91) 90.46,12.49 91,12.49 91.78,11.72 93.52,11.72 93.74,11.94 93.74,12.71 93.23,13.23 93.23,14.69 93.39,14.85 93.39,15.17 93.23,15.33 93.23,15.66 93.52,15.95 93.52,16.59 92.93,17.18 92.93,18.97 92.79,19.12 92.79,24.87 88.72,28.94 88.72,29.09 88.28,29.53 88.28,29.99 86.9,31.36 86.07,31.36 83.37,34.05 83.37,35.53 v2(83.86,36.01)
D1_MDQ1: length 45.8
  TOP w0.137: v2(85.41,33.37) 85.41,33.84 80.74,38.51 76.26,38.51 76.17,38.6 U14.A23 ; U15.F7 94.42,14.09 v2(93.83,14.09)
  L4_INT_2 w0.107: v2(85.41,33.37) 84.69,34.08 84.69,34.31 85.04,34.65 85.19,34.65 86.16,33.68 86.17,33.68 89.09,30.75 89.23,30.75 89.47,30.51 89.47,30.37 91.48,28.36 91.48,28.19 91.31,28.02 91.31,27.84 91.43,27.72 91.61,27.72 91.78,27.89 91.96,27.89 92.08,27.76 92.08,27.58 91.99,27.49 91.99,27.32 92.13,27.18 92.28,27.18 92.39,27.28 92.56,27.28 92.69,27.16 92.69,26.98 92.44,26.73 92.44,26.58 92.57,26.46 92.77,26.46 92.99,26.68 93.17,26.68 93.29,26.55 93.29,26.38 93.06,26.14 93.06,25.99 93.17,25.88 93.4,25.88 93.59,26.07 93.77,26.07 94.13,25.72 94.13,24.36 94.19,24.29 94.19,20.68 94.04,20.53 94.04,19.26 94.41,18.89 94.41,16.63 94.78,16.26 94.78,15.28 94.96,15.1 94.96,13.12 94.75,12.92 94.52,12.92 94.35,13.1 94.35,13.96 94.24,14.06 94.24,14.06 94.21,14.09 v2(93.83,14.09)
D1_MDQ2: length 45.7
  TOP w0.137: U15.H3 v2(90.84,12.91) ; U14.C26 74.2,35.82 75.58,35.82 75.82,35.57 79.4,35.57 79.7,35.27 v2(79.75,35.27)
  L4_INT_2 w0.107: v2(79.75,35.27) 79.75,36.28 79.46,36.57 78.93,36.57 78.63,36.27 78.63,30.85 84.62,24.86 84.79,24.86 85.28,25.34 85.45,25.34 85.58,25.22 85.58,25.04 85.09,24.56 85.09,24.38 85.22,24.26 85.4,24.26 85.88,24.74 86.06,24.74 86.18,24.62 86.18,24.44 85.7,23.96 85.7,23.78 85.82,23.65 86,23.65 86.48,24.14 86.66,24.14 86.78,24.01 86.78,23.84 86.3,23.35 86.3,23.17 86.43,23.05 86.6,23.05 87.09,23.53 87.26,23.53 87.39,23.41 87.39,23.23 86.9,22.75 86.9,22.57 87.03,22.45 87.21,22.45 87.69,22.93 87.87,22.93 87.99,22.81 87.99,22.63 87.51,22.14 87.51,21.97 88.7,20.77 88.7,15.28 89.1,14.89 89.4,14.89 89.62,14.67 89.62,14.13 v2(90.84,12.91)
D1_MDQ3: length 45.7
  TOP w0.137: v2(79.04,35.13) 75.69,35.13 U14.A27 ; v2(92.32,12.26) 92.57,12.51 U15.H7
  L4_INT_2 w0.107: v2(79.04,35.13) 79.04,31.66 79.24,31.46 79.41,31.46 79.91,31.95 80.09,31.95 80.21,31.83 80.21,31.65 79.72,31.16 79.72,30.98 79.84,30.85 80.02,30.85 80.51,31.35 80.69,31.35 80.82,31.23 80.82,31.05 80.32,30.55 80.32,30.38 80.44,30.25 80.62,30.25 81.12,30.75 81.29,30.75 81.42,30.62 81.42,30.45 80.92,29.95 80.92,29.77 81.05,29.65 81.23,29.65 81.72,30.14 81.9,30.14 82.02,30.02 82.02,29.84 81.53,29.35 81.53,29.17 81.65,29.04 81.83,29.04 82.32,29.54 82.5,29.54 82.63,29.41 82.63,29.24 82.03,28.64 82.03,28.46 82.15,28.34 82.33,28.34 82.95,28.96 83.13,28.96 83.23,28.86 83.23,28.63 82.73,28.14 82.73,27.96 83.18,27.51 83.44,27.51 84.92,26.03 85.33,26.03 85.56,26.26 86.02,26.26 89.62,22.65 89.62,18.67 89.62,18.67 89.62,15.56 91.26,13.92 91.26,12.82 91.82,12.26 v2(92.32,12.26)
D1_MDQ4: length 45.8
  TOP w0.137: U14.B22 75,39.77 76.19,39.77 76.26,39.84 81.39,39.84 84.6,36.62 v2(84.6,35.82) ; U15.H2 v2(90.84,12.11)
  L4_INT_2 w0.107: v2(84.6,35.82) 84.89,35.53 85.03,35.53 89.88,30.68 89.88,30.57 94.52,25.93 94.52,25.9 94.54,25.89 94.54,24.53 94.6,24.47 94.6,21.05 95.21,20.44 95.21,18.24 95.64,17.8 95.64,15.05 95.26,14.67 95.26,13.1 93.6,11.43 91.52,11.43 v2(90.84,12.11)
D1_MDQ5: length 45.7
  TOP w0.137: v2(97.52,13.61) 97.5,13.59 97.5,12.44 97.17,12.11 95.64,12.11 U15.H8 ; v2(83.86,36.75) 81.21,39.39 76.26,39.39 76.25,39.4 U14.A22
  L4_INT_2 w0.107: v2(83.86,36.75) 84.4,36.75 90.29,30.86 90.29,30.74 96.05,24.99 96.05,24.55 95.92,24.43 95.39,24.43 95.29,24.32 95.29,24.11 95.39,24 95.92,24 96.05,23.88 96.05,23.7 95.92,23.57 95.22,23.57 95.09,23.44 95.09,23.27 95.21,23.15 95.92,23.15 96.05,23.02 96.05,14.29 96.35,13.99 97.14,13.99 v2(97.52,13.61)
D1_MDQ6: length 45.7
  TOP w0.137: U15.J3 91.93,12.4 v2(91.93,12.82) ; U14.B25 75.03,36.59 76.01,36.59 76.15,36.45 79.8,36.45 82.01,34.24 82.01,34.03 v2(81.96,33.98)
  L4_INT_2 w0.107: v2(81.96,33.98) 82.02,33.98 82.12,34.08 82.74,34.08 82.89,34.23 82.89,36.57 82.53,36.92 81.01,36.92 80.7,36.61 80.7,33.81 80.33,33.43 80.33,32.53 83.64,29.21 83.64,28.22 84.87,26.99 85.42,26.99 85.75,26.67 86.19,26.67 90.03,22.82 90.03,21.83 90.76,21.1 90.76,20.02 90.43,19.7 90.43,15.06 91.48,14.01 91.48,13.36 91.89,12.96 91.89,12.86 v2(91.93,12.82)
D1_MDQ7: length 45.8
  TOP w0.137: U14.A26 75.8,36.2 75.98,36.01 79.62,36.01 81.29,34.34 v2(81.29,32.97) ; v2(93.36,12.1) 94.05,12.1 U15.J7
  L4_INT_2 w0.107: v2(93.36,12.1) 92.91,12.1 92.7,12.3 92.7,12.69 91.7,13.69 91.7,14.99 91.2,15.49 91.2,15.5 90.85,15.86 90.85,19.49 91.2,19.84 91.2,21.24 90.44,22 90.44,22.99 86.36,27.08 85.98,27.08 85.65,27.41 85.04,27.41 84.05,28.39 84.05,29.39 80.74,32.7 80.74,33.26 81.11,33.64 81.11,36.16 81.39,36.44 82.2,36.44 82.48,36.17 82.48,35.94 82.35,35.81 82.3,35.81 82.19,35.7 82.19,35.49 82.3,35.38 82.35,35.38 82.48,35.26 82.48,34.68 82.36,34.56 81.67,34.56 81.54,34.43 81.54,33.64 81.29,33.38 v2(81.29,32.97)
D1_MDQ8: length 48.9
  TOP w0.137: v2(91.82,18.14) 92.11,18.42 92.11,18.94 91.91,19.14 91.38,19.14 91.24,19 U15.A3 ; v3(71.82,39) U14.E22
  BOTTOM w0.137: v3(71.82,39) 71.7,38.88 71.7,38.71 71.84,38.57 72.05,38.57 72.22,38.74 72.22,39.62 72.22,39.63 72.22,40.04 72.21,40.05 72.21,40.12 72.31,40.22 74.57,40.22 74.71,40.09 74.71,39.66 74.88,39.49 76.12,39.49 78.55,37.06 78.55,36.45 79.21,35.78 79.21,35.69 79.08,35.55 78.83,35.55 78.61,35.34 78.61,34.81 78.53,34.73 78.53,34.3 78.68,34.15 79.29,34.15 79.43,34.01 79.43,33.4 82.33,30.5 83.28,30.5 84.77,29.01 85.41,29.01 86.07,29.67 86.36,29.67 93.48,22.55 93.48,22.3 93.28,22.1 93.28,21.86 93.48,21.66 93.48,21.46 93.28,21.26 93.28,20.97 93.48,20.76 93.48,19.78 94.58,18.68 94.58,17.42 94.43,17.27 94.43,16.56 94.3,16.42 93.54,16.42 93.37,16.59 93.37,16.74 92.97,17.14 92.97,17.54 92.81,17.71 91.76,17.71 91.66,17.81 91.66,17.97 v2(91.82,18.14)
D1_MDQ9: length 48.7
  TOP w0.137: v2(93.8,18.8) 94.68,19.68 97.57,19.68 97.8,19.45 97.8,17.29 97.62,17.11 97.42,17.11 97.17,17.37 97.17,18.74 96.96,18.94 95.31,18.94 94.84,18.47 94.84,17.71 U15.B8 ; v3(72.62,39) U14.D22
  BOTTOM w0.137: v2(93.8,18.8) 93.77,18.8 92.83,19.74 92.83,21.8 92.74,21.89 92.74,22.59 92.6,22.72 92.35,22.72 92.22,22.59 92.06,22.59 91.88,22.78 91.88,22.97 92.04,23.14 92.04,23.36 91.51,23.9 91.28,23.9 91.12,23.74 90.87,23.74 90.73,23.88 90.73,24.13 90.89,24.29 90.89,24.51 90.73,24.67 90.5,24.67 90.34,24.51 90.12,24.51 89.81,24.82 89.81,25.36 89.68,25.5 89.14,25.5 88.89,25.75 88.89,26.51 86.84,28.57 84.59,28.57 83.1,30.06 82.15,30.06 78.09,34.12 78.09,36.88 75.73,39.24 74.78,39.24 74.77,39.25 73.7,39.25 73.55,39.4 73.03,39.4 v3(72.62,39)
D1_MDQ10: length 48.8
  TOP w0.137: U15.C3 90.84,16.91 90.84,19.09 91.17,19.42 92.21,19.42 92.39,19.25 92.39,18.71 92.52,18.58 92.8,18.58 92.92,18.71 92.92,19.32 93.15,19.55 93.15,19.95 93.02,20.08 90.99,20.08 90.43,19.52 v2(89.11,19.52) ; v3(71.82,38.2) U14.F23
  BOTTOM w0.137: v3(71.82,38.2) 72.22,37.8 72.22,37.23 72.45,37 72.86,37 73.03,36.83 73.03,36.48 73.05,36.45 73.05,36.32 73.2,36.17 73.58,36.17 73.8,35.95 73.8,35.64 73.58,35.42 73.16,35.42 72.99,35.24 72.99,33.69 81.62,25.05 85.64,25.05 85.83,24.87 85.83,24.64 85.42,24.23 85.42,24 85.58,23.84 85.81,23.84 86.22,24.25 86.44,24.25 86.61,24.09 86.61,23.86 86.19,23.45 86.19,23.22 86.35,23.06 86.58,23.06 86.99,23.47 87.22,23.47 87.38,23.31 87.38,23.09 86.97,22.67 86.97,22.45 87.13,22.29 87.36,22.29 87.77,22.7 88,22.7 88.16,22.54 88.16,22.31 87.75,21.9 87.75,21.67 87.91,21.51 88.13,21.51 88.55,21.92 88.77,21.92 89.11,21.58 89.11,21.25 88.95,21.09 88.31,21.09 88.15,20.92 88.15,20.7 88.31,20.54 88.95,20.54 89.11,20.38 v2(89.11,19.52)
D1_MDQ11: length 48.7
  TOP w0.137: U15.C7 93.91,16.51 93.32,17.1 93.32,19.11 v2(94.45,20.24) ; v3(71.02,38.2) U14.G23
  BOTTOM w0.137: v2(94.45,20.24) 94.45,22.83 86.73,30.55 86.4,30.55 84.11,32.85 83.92,32.85 83.76,32.69 83.76,31.81 83.59,31.63 83.2,31.63 83.06,31.77 83.06,32.84 82.92,32.97 82.2,32.97 81.54,33.64 81.54,34.14 81.4,34.27 80.89,34.27 80.73,34.43 80.73,34.66 80.89,34.82 81.49,34.82 81.63,34.96 81.63,35.3 81.48,35.44 80.8,35.44 80.64,35.6 80.64,35.95 80.37,36.22 80.02,36.22 79.86,36.38 79.86,36.61 79.96,36.7 79.96,36.93 76.02,40.86 73.43,40.86 73.05,41.24 73.05,41.51 72.77,41.79 71.69,41.79 71.45,41.55 71.45,41.29 71.16,41 70.9,40.99 70.65,40.75 70.65,38.84 70.87,38.62 71.08,38.62 71.16,38.55 71.16,38.33 v3(71.02,38.2)
D1_MDQ12: length 48.8
  TOP w0.137: U15.C2 90.84,16.11 91.41,16.11 91.64,16.34 91.64,16.35 91.78,16.49 v2(91.8,16.49) ; v3(70.22,39) U14.G22
  BOTTOM w0.137: v2(91.8,16.49) 92.35,16.49 92.67,16.17 94.68,16.17 95.24,16.73 95.24,19.31 94.93,19.63 94.93,22.97 86.91,30.99 86.59,30.99 75.78,41.8 73.26,41.8 73.02,42.03 73.02,42.32 72.75,42.6 71.66,42.6 71.4,42.33 71.4,42.01 71.16,41.77 70.87,41.77 70.6,41.5 70.6,41.23 70.33,40.97 70.07,40.97 69.82,40.72 69.82,39.4 v3(70.22,39)
D1_MDQ13: length 48.7
  TOP w0.137: v3(71.02,39) U14.F22 ; U15.C8 v2(94.84,16.91)
  BOTTOM w0.137: v2(94.84,16.91) 94.83,16.92 94.83,19.06 93.92,19.97 93.92,22.73 86.55,30.11 85.89,30.11 85.23,29.45 84.95,29.45 84.8,29.6 84.8,29.8 85.55,30.55 85.55,30.78 85.39,30.94 85.16,30.94 84.41,30.19 84.22,30.19 84.02,30.38 84.02,30.57 84.78,31.33 84.78,31.55 84.59,31.74 84.32,31.74 83.54,30.96 82.64,30.96 82.39,31.21 82.39,31.56 82.49,31.66 82.49,31.89 82.3,32.08 81.54,32.08 80.74,32.88 80.74,33.08 81.09,33.43 81.09,33.67 80.95,33.8 80.72,33.8 80.47,33.55 80.46,33.55 80.36,33.45 80.16,33.45 79.87,33.75 79.87,34.26 80.29,34.68 80.29,34.84 80.35,34.91 80.35,35.27 78.99,36.63 78.99,37.27 76.46,39.8 75.23,39.8 75.09,39.93 75.09,40.1 74.67,40.52 74.67,40.53 73.4,40.53 72.94,41 71.7,41 71.4,40.7 71.4,39.13 71.26,39 v3(71.02,39)
D1_MDQ14: length 48.7
  TOP w0.137: U15.D3 91.67,15.28 92.72,15.28 92.84,15.41 93.17,15.41 93.27,15.31 94.68,15.31 94.84,15.47 94.84,15.97 94.7,16.11 92.26,16.11 v2(91.89,15.74) ; v3(74.23,38.19) 73.83,37.8 U14.C24
  BOTTOM w0.137: v3(74.23,38.19) 73.85,37.82 73.85,37.24 74.1,36.99 74.39,36.99 74.86,36.52 75.09,36.52 75.62,37.05 75.85,37.05 76.01,36.89 76.01,36.67 75.48,36.13 75.48,35.9 75.91,35.48 75.91,32.04 81.95,25.99 86.17,25.99 91.27,20.88 91.27,18.38 90.89,17.99 90.89,17.76 91.23,17.42 91.23,17.2 91.07,17.04 90.84,17.04 90.5,17.38 90.27,17.38 90.08,17.18 90.08,16.77 90.44,16.41 90.44,15.8 90.58,15.66 90.63,15.66 90.68,15.71 91.01,15.71 91.32,15.39 91.32,15.21 90.94,14.83 90.94,14.63 91.24,14.34 91.46,14.34 91.76,14.63 91.76,14.9 92.17,15.31 92.17,15.45 v2(91.89,15.74)
D1_MDQ15: length 48.7
  TOP w0.137: U15.D7 v2(93.82,15.71) ; v3(72.62,38.2) U14.E23
  BOTTOM w0.137: v3(72.62,38.2) 73.01,37.81 73.01,37.23 73.24,37 73.59,37 73.82,36.76 73.82,36.28 74.05,36.05 74.05,35.86 74.43,35.48 75.37,35.48 75.59,35.26 75.59,33.45 75.47,33.33 75.47,33.32 75.25,33.1 75.25,32.06 81.79,25.51 86.02,25.51 90.82,20.71 90.82,18.61 90.32,18.11 89.88,18.11 89.64,17.87 89.64,16.63 89.52,16.51 89.01,16.51 88.78,16.28 88.78,15.64 88.66,15.51 88.15,15.51 88.06,15.42 88.06,15.02 88.17,14.91 90.25,14.91 90.44,14.72 90.44,13.55 90.6,13.39 91.91,13.39 92.04,13.52 92.04,14.62 92.28,14.85 92.29,14.85 92.84,15.41 93.23,15.41 93.46,15.18 93.46,14.75 93.71,14.5 94.14,14.5 94.32,14.67 94.32,15.61 94.22,15.71 v2(93.82,15.71)
D1_MDQ16: length 49.1
  TOP w0.137: v3(73.43,35.79) 73.02,36.2 U14.D26 ; U16.G2 v2(78.56,13.71)
  L4_INT_2 w0.107: v3(73.43,35.79) 73.43,36.1 73.53,36.21 74.38,36.21 74.74,36.57 74.97,36.57 75.12,36.71 75.4,36.71 75.55,36.57 75.83,36.57 75.97,36.71 76.25,36.71 76.4,36.57 76.95,36.57 77.28,36.24 77.28,32.52 77.38,32.41 77.51,32.41 77.61,32.3 77.61,32.09 77.51,31.98 77.38,31.98 77.28,31.88 77.28,31.66 77.38,31.56 77.51,31.56 77.61,31.45 77.61,31.24 77.51,31.13 77.38,31.13 77.28,31.02 77.28,30.4 84.53,23.14 84.53,22.49 84.7,22.33 84.7,22.17 84.63,22.11 84.63,21.95 84.78,21.8 84.93,21.8 85,21.87 85.15,21.87 85.3,21.72 85.3,21.57 85.23,21.5 85.23,21.35 85.39,21.2 85.54,21.2 85.61,21.27 85.76,21.27 85.91,21.12 85.91,20.97 85.84,20.9 85.84,20.75 85.99,20.6 86.14,20.6 86.21,20.67 86.36,20.67 87.25,19.77 87.25,14.29 87.23,14.27 87.23,13.04 87.12,12.93 85.48,12.93 85.12,13.29 83.2,13.29 82.93,13.02 82.61,13.02 82.5,13.13 82.5,14.72 82.39,14.83 82,14.83 81.89,14.72 81.89,13.13 81.79,13.02 81.42,13.02 81.32,13.13 81.32,13.43 81.19,13.55 79.98,13.55 79.87,13.66 79.87,14.05 79.74,14.18 79.57,14.18 79.44,14.05 79.44,13.54 79.34,13.43 79.11,13.43 78.84,13.71 v2(78.56,13.71)
D1_MDQ17: length 49.1
  TOP w0.137: U16.F7 v2(83.36,14.51)
  TOP w0.381: U14.E24 v3(72.63,37.39)
  L4_INT_2 w0.107: v2(83.36,14.51) 82.92,14.51 82.75,14.68 82.75,15.37 83.07,15.69 85.48,15.69 85.58,15.8 85.58,16.42 85.48,16.52 83.08,16.52 82.92,16.69 82.92,17.14 83.07,17.29 85.44,17.29 85.57,17.42 85.57,17.93 85.38,18.12 83.59,18.12 83.48,18.23 83.48,19.49 83.59,19.6 85.17,19.6 85.34,19.78 85.34,20.02 84.52,20.84 84.37,20.84 83.98,20.45 83.83,20.45 83.68,20.6 83.68,20.76 84.07,21.14 84.07,21.3 81.61,23.75 81.61,24.9 76.45,30.05 76.45,33.79 76.35,33.9 75.86,33.9 75.76,34.01 75.76,34.22 75.86,34.33 76.35,34.33 76.45,34.43 76.45,34.65 76.35,34.75 75.86,34.75 75.76,34.86 75.76,35.07 75.86,35.18 76.35,35.18 76.45,35.29 76.45,35.73 76.35,35.83 75.07,35.83 74.64,35.4 74.64,34.6 74.53,34.5 73.24,34.5 72.24,35.5 72.24,37.01 v3(72.63,37.39)
D1_MDQ18: length 49.2
  TOP w0.137: v3(71.03,37.39) 70.89,37.53 70.89,37.53 U14.G24 ; U16.H3 80.02,12.51 v2(80.45,12.08)
  L4_INT_2 w0.107: v3(71.03,37.39) 70.58,36.95 69.28,36.95 69.04,36.71 69.04,35.64 69.1,35.58 69.1,34.93 68.72,34.55 68.72,32.79 68.94,32.57 68.94,32.32 69.14,32.12 69.39,32.12 69.54,31.97 69.54,31.82 69.46,31.74 69.46,31.58 69.61,31.43 69.76,31.43 69.84,31.52 69.99,31.52 70.14,31.37 70.14,31.22 70.06,31.13 70.06,30.98 70.21,30.83 70.36,30.83 70.45,30.91 70.6,30.91 70.75,30.76 70.75,30.61 70.66,30.53 70.66,30.38 70.81,30.23 70.96,30.23 71.05,30.31 71.2,30.31 71.79,29.72 71.79,27.66 72,27.45 72.17,27.29 72.16,27.14 71.78,26.75 71.78,26.6 71.93,26.45 72.09,26.45 72.47,26.83 72.62,26.83 73.41,26.04 74.05,26.04 74.53,25.56 74.53,25.41 74.46,25.33 74.46,25.18 74.61,25.03 74.76,25.03 74.84,25.11 74.99,25.11 75.14,24.95 75.14,24.8 75.06,24.73 75.06,24.58 75.21,24.42 75.36,24.42 75.44,24.5 75.59,24.5 75.74,24.35 75.74,24.2 75.66,24.12 75.66,23.97 75.81,23.82 75.97,23.82 76.04,23.9 76.19,23.9 76.35,23.75 76.35,23.6 76.27,23.52 76.27,23.37 76.42,23.22 76.57,23.22 76.65,23.29 76.8,23.29 76.95,23.14 76.95,22.99 76.87,22.92 76.87,22.76 77.02,22.61 77.17,22.61 77.25,22.69 77.4,22.69 77.55,22.54 77.55,22.39 77.47,22.31 77.47,22.16 77.63,22.01 77.78,22.01 77.85,22.09 78,22.09 78.78,21.32 78.78,19.6 78.49,19.31 76.13,19.31 75.76,18.94 75.76,18.42 75.88,18.29 76.74,18.29 76.85,18.18 76.85,17.97 76.74,17.86 75.88,17.86 75.76,17.74 75.76,16.31 75.88,16.19 76.21,16.19 76.34,16.06 76.34,15.88 76.21,15.76 75.89,15.76 75.78,15.65 75.78,14.94 75.75,14.91 75.75,12.56 76.22,12.08 77.85,12.08 77.97,11.96 77.97,11.75 78.1,11.63 78.28,11.63 78.4,11.75 78.4,11.96 78.53,12.08 78.7,12.08 78.83,11.96 78.83,11.75 78.95,11.63 79.13,11.63 79.25,11.75 79.25,11.96 79.38,12.08 v2(80.45,12.08)
D1_MDQ19: length 49.1
  TOP w0.137: U14.H25 70.09,36.73 70.09,36.73 v3(70.23,36.59) ; U16.H7 v2(83.36,12.91)
  L4_INT_2 w0.107: v2(83.36,12.91) 82.03,11.57 81.21,11.57 81.01,11.78 81.01,12.27 80.79,12.49 77.54,12.49 77.53,12.49 77.15,12.49 76.9,12.75 76.9,14.06 77.31,14.47 77.31,14.71 77.16,14.85 76.27,14.85 76.19,14.92 76.19,15.2 76.27,15.27 77.2,15.27 77.34,15.42 77.34,16.57 77.19,16.72 76.29,16.72 76.18,16.82 76.18,17.04 76.29,17.14 77.16,17.14 77.28,17.26 77.28,18.63 77.29,18.64 77.29,18.66 77.63,19 78.06,19 78.18,18.88 78.18,18.35 78.42,18.11 78.71,18.11 79.03,18.43 79.03,19.14 79.33,19.45 80.25,19.45 80.33,19.52 80.33,20.28 80.22,20.39 79.91,20.39 79.45,19.93 79.29,19.93 79.19,20.04 79.19,20.27 79.64,20.73 79.64,21.03 74.22,26.46 73.58,26.46 73.31,26.73 73.31,27.37 72.98,27.7 72.83,27.7 72.66,27.53 72.5,27.53 72.35,27.68 72.35,27.83 72.52,28 72.52,28.15 72.2,28.47 72.2,29.89 69.34,32.75 69.34,33.66 69.24,33.77 69.08,33.77 68.98,33.87 68.98,34.09 69.08,34.2 69.24,34.2 69.34,34.3 69.34,35.14 69.84,35.63 69.84,36.46 69.97,36.59 v3(70.23,36.59)
D1_MDQ20: length 49.1
  TOP w0.137: U14.C25 73.83,37 v3(74.23,37.39) ; U16.H2 78.56,12.11 77.64,12.11 77.21,12.54 75.42,12.54 v2(74.78,13.19)
  L4_INT_2 w0.107: v2(74.78,13.19) 74.78,18.63 76.09,19.95 78.21,19.95 78.36,20.1 78.36,20.69 77.82,21.23 77.67,21.23 76.85,20.41 76.7,20.41 76.55,20.56 76.55,20.71 77.37,21.53 77.37,21.69 77.22,21.84 77.07,21.84 76.25,21.02 76.1,21.02 75.94,21.17 75.94,21.32 76.76,22.14 76.76,22.29 73.42,25.63 73.19,25.63 72.98,25.85 71.82,25.85 71.21,26.47 71.21,27.11 71.37,27.27 71.37,27.53 71.21,27.7 71.21,27.96 71.37,28.12 71.37,28.39 71.21,28.55 71.21,29.25 70.96,29.49 70.96,29.5 68.09,32.37 68.09,35.52 68.21,35.64 68.21,37.48 68.51,37.78 73.84,37.78 v3(74.23,37.39)
D1_MDQ21: length 49.1
  TOP w0.137: U16.H8 v2(84.16,12.91) ; v3(73.43,36.59) U14.D25
  L4_INT_2 w0.107: v2(84.16,12.91) 84.55,12.52 88.6,12.52 88.86,12.78 88.86,13.14 88.75,13.24 88.21,13.24 88.1,13.35 88.1,13.56 88.21,13.67 88.75,13.67 88.86,13.78 88.86,14.01 87.91,14.95 87.91,15.11 88.02,15.21 88.17,15.21 88.29,15.34 88.29,15.51 88.17,15.64 87.89,15.64 87.77,15.76 87.77,16.86 87.87,16.96 88.19,16.96 88.29,17.07 88.29,17.28 88.19,17.39 87.87,17.39 87.77,17.5 87.77,17.71 87.87,17.82 88.19,17.82 88.29,17.92 88.29,18.14 88.19,18.24 87.87,18.24 87.77,18.35 87.77,19.84 87.12,20.49 87.12,20.64 87.61,21.13 87.61,21.28 87.46,21.43 87.31,21.43 86.82,20.94 86.67,20.94 86.52,21.09 86.52,21.24 87.01,21.73 87.01,21.88 86.86,22.03 86.71,22.03 86.22,21.54 86.07,21.54 85.92,21.69 85.92,21.84 86.41,22.34 86.41,22.49 86.26,22.64 86.11,22.64 85.61,22.14 85.46,22.14 84.95,22.66 84.95,23.68 78.14,30.49 78.14,32.77 77.76,33.15 77.76,33.92 77.86,34.03 78.07,34.03 78.17,34.13 78.17,34.35 78.07,34.45 77.86,34.45 77.76,34.56 77.76,34.77 77.86,34.88 78.07,34.88 78.17,34.99 78.17,35.2 78.07,35.31 77.86,35.31 77.76,35.41 77.76,35.63 77.86,35.73 78.07,35.73 78.17,35.84 78.17,36.05 78.07,36.16 77.86,36.16 77.76,36.27 77.76,36.62 77.4,36.98 73.81,36.98 v3(73.43,36.59)
D1_MDQ22: length 49.1
  TOP w0.137: U14.G25 70.62,37 v3(71.03,36.59) ; v2(80.89,13.17) 81.29,13.57 81.98,13.57 82.02,13.52 82.27,13.52 82.41,13.38 82.41,13.08 82.26,12.93 81.97,12.93 81.54,12.5 81.43,12.5 80.62,11.68 79.79,11.68 U16.J3
  L4_INT_2 w0.107: v3(71.03,36.59) 70.64,36.21 70.64,35.49 70.77,35.36 70.77,34.06 71.09,33.75 71.45,33.75 71.65,33.95 72.19,33.95 72.3,33.85 72.3,32.71 72.47,32.54 72.62,32.54 73.26,33.18 73.41,33.18 73.68,32.92 73.68,32.77 73.04,32.12 73.04,31.97 73.49,31.51 73.49,28.35 74.27,27.57 74.42,27.57 74.63,27.77 74.78,27.77 74.93,27.62 74.93,27.47 74.72,27.27 74.72,27.12 74.87,26.96 75.03,26.96 75.23,27.17 75.38,27.17 75.53,27.02 75.53,26.87 75.33,26.66 75.33,26.51 75.48,26.36 75.63,26.36 75.83,26.57 75.99,26.57 76.14,26.42 76.14,26.27 75.93,26.06 75.93,25.91 81.44,20.4 81.44,20.29 81.55,20.18 81.89,20.18 81.99,20.07 81.99,19.86 81.89,19.75 81.55,19.75 81.44,19.65 81.44,19.17 80.93,18.66 80.48,18.66 79.8,17.99 79.8,17.21 80.69,16.32 80.69,16.17 80.44,15.91 80.28,15.91 79.68,16.51 79.53,16.51 79.38,16.36 79.38,16.17 80.14,15.41 80.14,15.26 80.04,15.15 79.76,15.15 79.04,15.87 78.89,15.87 78.78,15.76 78.78,15.6 79.17,15.22 79.17,14.86 78.98,14.67 78.98,14.53 78.98,14.53 78.98,14.35 78.72,14.09 78.39,14.09 78.16,13.86 78.16,13.46 78.45,13.17 v2(80.89,13.17)
D1_MDQ23: length 49.2
  TOP w0.137: U16.J7 v2(82.14,12.53) ; v3(70.23,35.79) 69.82,36.2 U14.H26
  L4_INT_2 w0.107: v3(70.23,35.79) 70.23,35.54 69.66,34.97 69.66,34.61 69.76,34.51 70.15,34.51 70.26,34.4 70.26,34.19 70.15,34.08 69.76,34.08 69.66,33.97 69.66,33.02 70.07,32.6 70.22,32.6 71.09,33.47 71.28,33.47 71.43,33.32 71.43,33.17 70.55,32.28 70.55,32.13 70.68,32 70.89,32 71.58,32.69 71.73,32.69 71.88,32.54 71.88,32.39 71.16,31.67 71.16,31.51 71.28,31.39 71.43,31.39 72.05,32.02 72.32,32.02 72.47,31.87 72.47,31.72 71.79,31.03 71.79,30.88 71.9,30.78 72.05,30.78 72.16,30.89 72.31,30.89 72.46,30.74 72.46,30.59 72.35,30.47 72.35,30.32 72.66,30.02 72.66,29.7 72.76,29.59 72.97,29.59 73.08,29.49 73.08,29.27 72.97,29.17 72.76,29.17 72.66,29.06 72.66,28.6 80.74,20.52 80.74,20.22 80.84,20.12 80.92,20.12 81.05,19.99 81.05,19.82 80.92,19.69 80.84,19.69 80.74,19.58 80.74,19.35 80.17,18.78 80.02,18.78 79.74,19.06 79.56,19.06 79.44,18.94 79.44,18.76 79.7,18.5 79.7,18.32 79.54,18.15 79.21,18.15 78.98,17.92 78.98,17.07 78.98,17.07 78.98,16.69 78.87,16.58 78.66,16.58 78.55,16.69 78.55,16.95 78.44,17.06 78.25,17.06 78.15,16.95 78.15,15.73 78.25,15.62 78.43,15.62 78.54,15.51 78.54,15.3 78.43,15.19 78.25,15.19 78.15,15.09 78.15,14.35 77.92,14.12 77.54,14.12 77.31,13.89 77.31,13.4 77.39,13.32 77.91,13.32 78.48,12.76 81.28,12.76 81.42,12.62 81.42,12 81.53,11.9 81.96,11.9 82.14,12.07 v2(82.14,12.53)
D1_MDQ24: length 46.4
  TOP w0.137: v3(68.63,38.19) 68.22,38.6 U14.K23 ; v2(84.8,19.21) 84.25,19.21 84.25,19.21 80.86,19.21 U16.A3
  BOTTOM w0.137: v3(68.63,38.19) 68.25,38.57 68.25,39.15 68.49,39.39 68.91,39.39 69.05,39.26 69.05,38.78 69.21,38.62 69.61,38.62 69.8,38.43 69.8,38.38 69.82,38.36 69.82,37.13 69.96,36.99 70.39,36.99 70.62,36.76 70.62,36.47 70.89,36.2 71.19,36.2 71.19,36.2 71.24,36.2 71.45,35.98 71.45,35.37 71.36,35.28 71.36,32.99 72.22,32.12 72.22,31.05 72.47,30.8 73.9,30.8 74.59,30.1 74.59,29.35 75.88,28.06 76.61,28.06 79.89,24.78 79.89,23.79 80.48,23.2 83.59,23.2 86.62,20.16 86.62,16.57 86.45,16.39 86.1,16.39 85.97,16.53 85.97,18.94 85.7,19.21 v2(84.8,19.21)
D1_MDQ25: length 46.5
  TOP w0.137: v3(69.43,37.39) 69.02,37.79 U14.J24 ; U16.B8 v2(84.16,17.71)
  BOTTOM w0.137: v3(69.43,37.39) 69.43,37.12 69.85,36.69 69.85,36.44 70.1,36.19 70.35,36.19 70.62,35.92 70.62,35.34 70.76,35.21 70.9,35.21 71.05,35.05 71.05,34.81 70.9,34.66 70.76,34.66 70.62,34.52 70.62,34.25 70.76,34.11 70.97,34.11 71.11,33.97 71.11,33.7 70.97,33.56 70.79,33.56 70.66,33.42 70.66,33 71.78,31.88 71.78,30.84 72.78,29.84 73.47,29.84 73.66,29.65 73.66,29.46 73.56,29.35 73.56,29.16 73.75,28.96 73.95,28.96 74.05,29.07 74.25,29.07 75.85,27.47 76.58,27.47 77.81,26.24 77.81,25.25 78.41,24.64 78.67,24.64 78.9,24.88 79.1,24.88 79.29,24.69 79.29,24.49 79.02,24.23 79.02,24.03 80.33,22.72 80.94,22.72 81.07,22.59 81.07,22.46 81.21,22.33 81.49,22.33 81.62,22.46 81.62,22.59 81.76,22.72 82.03,22.72 82.17,22.59 82.17,22.46 82.31,22.33 82.58,22.33 82.72,22.46 82.72,22.59 82.86,22.72 83.38,22.72 83.65,22.45 83.65,22.26 83.3,21.91 83.3,21.71 83.44,21.58 83.63,21.58 83.98,21.92 84.24,21.92 84.4,21.76 84.4,21.52 84.16,21.28 84.16,21.06 84.33,20.89 84.54,20.89 84.8,21.15 85.01,21.15 85.72,20.44 85.72,19.74 85.58,19.61 84.29,19.61 83.75,19.07 83.75,18.28 83.92,18.11 85.23,18.11 85.45,17.89 85.45,14.59 85.31,14.45 84.79,14.45 84.56,14.68 84.56,17.31 v2(84.16,17.71)
D1_MDQ26: length 46.4
  TOP w0.137: U16.C3 v2(79.36,16.91) ; v3(67.83,37.39) 67.42,37.79 U14.L24
  BOTTOM w0.137: v2(79.36,16.91) 79.1,16.91 78.96,17.05 78.96,18.85 78.5,19.31 76.66,19.31 76.26,18.92 76.26,15.82 76.4,15.69 77.12,15.69 77.23,15.58 77.23,15.3 77.1,15.17 76.15,15.17 76.01,15.03 76.01,14.58 75.49,14.05 74.39,14.05 74.26,14.19 74.26,14.42 74.38,14.55 74.85,14.55 74.97,14.67 74.97,14.86 74.81,15.03 74.4,15.03 74.32,15.11 74.32,19.7 73.96,20.06 72.16,20.06 72.16,20.06 70.21,20.06 69.49,20.78 69.49,27.14 66.78,29.86 66.78,31.64 66,32.42 66,35.35 65.8,35.55 65.8,36.74 66.06,37 67.19,37 67.59,37.4 67.82,37.4 v3(67.83,37.39)
D1_MDQ27: length 46.4
  TOP w0.137: U16.C7 v2(83.36,16.91) ; U14.M24 66.62,37.79 v3(67.03,37.39)
  BOTTOM w0.137: v2(83.36,16.91) 83.36,16.84 80.66,14.14 80.66,13.56 80.52,13.42 79.9,13.42 79.76,13.56 79.76,14.8 79.41,15.15 78.2,15.15 77.95,14.91 77.48,14.91 76.75,14.18 76.75,14.05 76.47,13.77 76.1,13.77 75.95,13.61 74.25,13.61 73.88,13.99 73.88,18.67 73.88,18.68 73.88,19.43 73.69,19.62 71.97,19.62 71.97,19.62 70.02,19.62 69.05,20.6 69.05,20.69 69.05,26.96 66.33,29.67 66.33,31.46 65.56,32.23 65.56,32.45 64.98,33.02 64.98,37.48 65.3,37.79 66.63,37.79 v3(67.03,37.39)
D1_MDQ28: length 46.4
  TOP w0.137: v2(80.49,17.09) 80.54,17.14 80.54,17.51 80.82,17.8 81.06,17.8 81.26,17.6 81.26,16.33 81.04,16.11 79.36,16.11 U16.C2 ; v3(68.62,39) U14.J22
  BOTTOM w0.137: v2(80.49,17.09) 80.69,17.3 81.28,17.3 81.81,17.83 81.81,18.41 81.63,18.59 80.23,18.59 78.63,20.2 75.16,20.2 74.34,21.01 70.55,21.01 70.42,21.15 70.42,21.62 70.55,21.76 71.31,21.76 71.44,21.9 71.44,22.17 71.31,22.31 70.55,22.31 70.42,22.45 70.42,22.72 70.55,22.86 71.31,22.86 71.44,23 71.44,23.27 71.31,23.41 70.55,23.41 70.42,23.54 70.42,23.82 70.55,23.96 71.31,23.96 71.44,24.09 71.44,24.37 71.31,24.5 70.55,24.5 70.42,24.64 70.42,27.8 67.95,30.27 67.95,31.14 67.74,31.34 67.74,31.63 67.95,31.84 67.95,32.37 67.72,32.6 67.72,32.96 67.95,33.19 67.95,33.73 67.55,34.13 67.55,35.45 67.41,35.59 67.41,35.97 67.65,36.21 68.01,36.21 68.23,36.43 68.23,37.56 68.46,37.8 68.85,37.8 69,37.95 69,38.45 68.62,38.82 v3(68.62,39)
D1_MDQ29: length 46.4
  TOP w0.137: v3(70.23,38.19) 70.09,38.33 70.09,38.33 U14.H23 ; U16.C8 v2(84.16,16.91)
  BOTTOM w0.137: v3(70.23,38.19) 70.26,38.16 70.26,37.94 70.62,37.58 70.62,37.15 70.78,36.99 71.09,36.99 71.11,36.97 71.18,36.97 71.4,36.75 71.4,36.68 71.42,36.66 71.42,36.36 71.59,36.19 71.99,36.19 72.22,35.96 72.22,35.16 72.22,33.75 72.25,33.72 72.25,33.11 72.62,32.73 72.62,32.7 75.81,29.51 75.81,28.75 76.06,28.51 76.79,28.51 80.33,24.96 80.33,23.97 80.58,23.72 80.93,23.72 81.34,24.13 81.85,24.13 82.26,23.72 82.61,23.72 82.92,24.04 83.46,24.04 87.17,20.32 87.17,13.69 87.04,13.55 85.73,13.55 85.59,13.69 85.59,13.97 85.45,14.11 84,14.11 84,14.11 83.02,14.11 82.75,13.84 82.75,13.53 82.61,13.39 82.15,13.39 82.01,13.53 82.01,14.76 v2(84.16,16.91)
D1_MDQ30: length 46.4
  TOP w0.137: U14.K24 68.22,37.79 v3(68.63,37.39) ; U16.D3 v2(80.8,15.71)
  BOTTOM w0.137: v3(68.63,37.39) 68.77,37.39 69,37.16 69,35.52 69.25,35.27 69.25,33.15 69.39,33.01 69.6,33.01 69.74,32.87 69.74,32.6 69.6,32.46 69.44,32.46 69.3,32.33 69.3,30.9 69.58,30.62 69.77,30.62 70.19,31.04 70.38,31.04 70.58,30.84 70.58,30.65 70.16,30.24 70.16,30.04 70.36,29.85 70.55,29.85 70.94,30.24 71.13,30.24 71.33,30.04 71.33,29.85 70.94,29.46 70.94,29.27 71.13,29.07 71.33,29.07 71.72,29.46 71.91,29.46 72.1,29.27 72.1,29.07 71.71,28.68 71.71,28.49 71.91,28.3 72.1,28.3 72.49,28.68 72.68,28.68 72.88,28.49 72.88,28.3 72.49,27.91 72.49,27.71 72.82,27.38 72.82,26.52 73.57,25.77 74.5,25.77 74.9,25.38 75.12,25.38 75.77,26.03 75.97,26.03 76.16,25.83 76.16,25.64 75.49,24.98 75.49,24.78 76.27,24 77.65,24 80.21,21.44 82.31,21.44 82.94,20.81 82.94,17.63 82.51,17.2 81.53,17.2 80.84,16.51 78.4,16.51 78.16,16.27 78.16,15.94 78.4,15.71 80.8,15.71 v2(80.8,15.71)
